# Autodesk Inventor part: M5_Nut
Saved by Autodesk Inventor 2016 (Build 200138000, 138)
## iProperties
Created: 2015-11
Part Number: M5_Nut
Material: Generic
Document SubType Name: Modeling
Designer: John
Density: 1 g/cm^3
Appearance: Default
Author: John
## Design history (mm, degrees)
feature "Base1"
body "Solid1"
